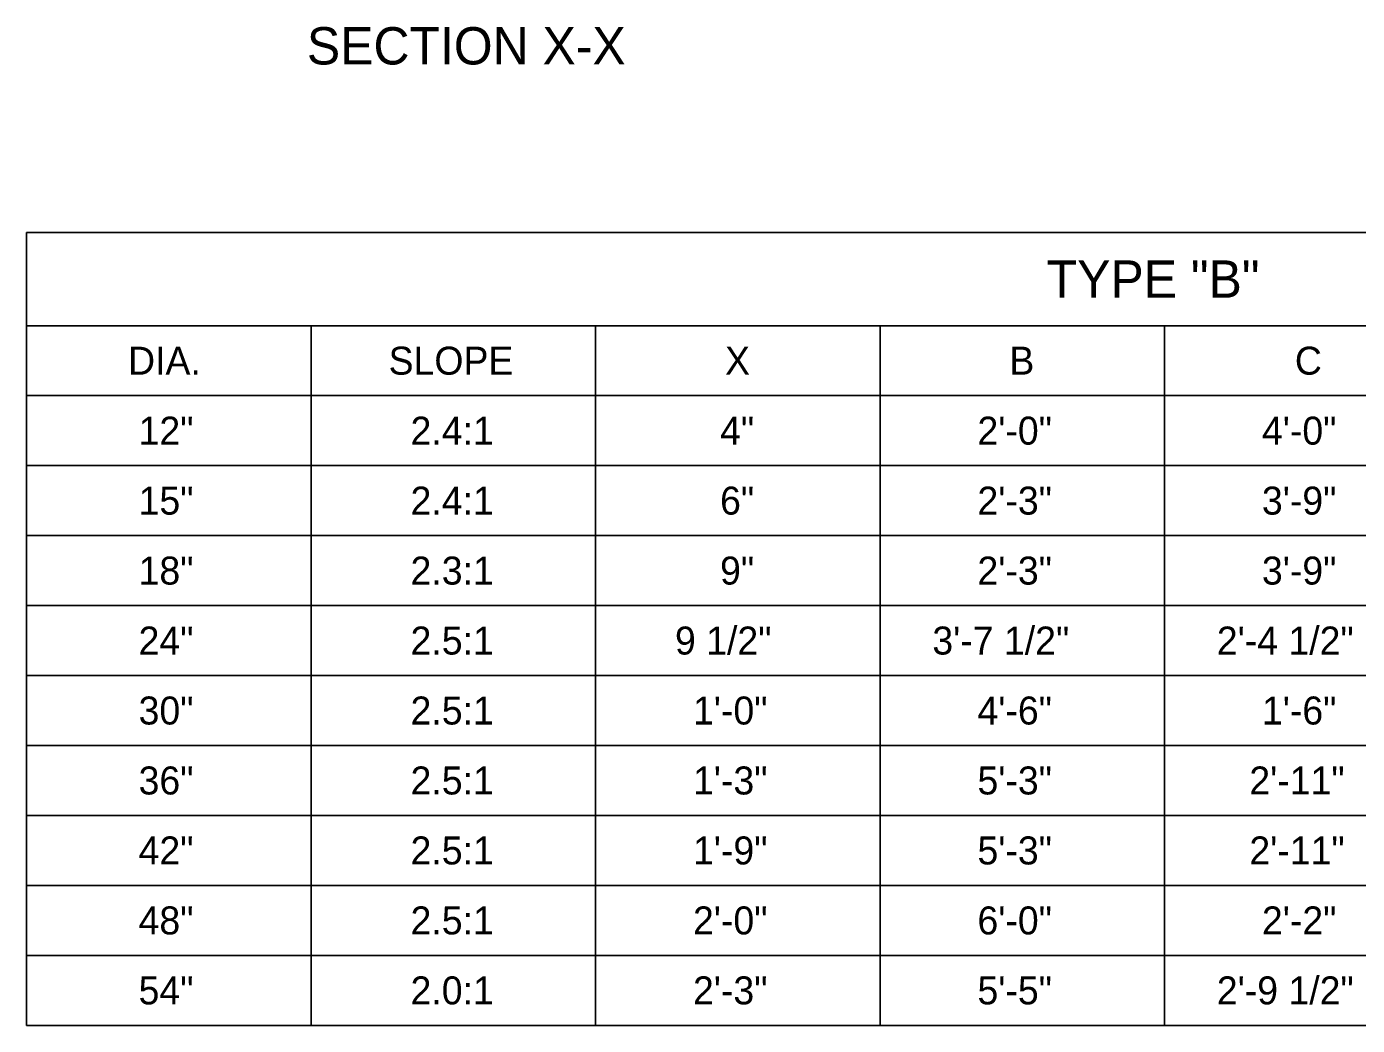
# Model space of a CAD drawing. Extents: x 49991.4 to 50021, y 49987.6 to 50011.4.
# Drawn here: x 50009.616 to 50012.469, y 49992.977 to 49995.118 of the extents above; entities that cross this region are included whole.
import ezdxf

# ---------------------------------------------------------------- set-up
doc = ezdxf.new("R2010")
doc.units = 0
doc.layers.add('Level 2', color=7, linetype='Continuous')

msp = doc.modelspace()

# ---------------------------------------------------------------- linework, layer by layer
at = {"layer": 'Level 2'}
for p, q in [((50009.6159, 49994.677), (50014.4959, 49994.677)), ((50009.6159, 49994.677), (50009.6159, 49992.977)), ((50009.6159, 49994.477), (50014.4959, 49994.477)), ((50010.2259, 49994.477), (50010.2259, 49992.977)), ((50010.8359, 49994.477), (50010.8359, 49992.977)), ((50011.4459, 49994.477), (50011.4459, 49992.977)), ((50012.0559, 49994.477), (50012.0559, 49992.977)), ((50009.6159, 49994.327), (50014.4959, 49994.327)), ((50009.6159, 49994.177), (50014.4959, 49994.177)), ((50009.6159, 49994.027), (50014.4959, 49994.027)), ((50009.6159, 49993.877), (50014.4959, 49993.877)), ((50009.6159, 49993.727), (50014.4959, 49993.727)), ((50009.6159, 49993.577), (50014.4959, 49993.577)), ((50009.6159, 49993.427), (50014.4959, 49993.427)), ((50009.6159, 49993.277), (50014.4959, 49993.277)), ((50009.6159, 49993.127), (50014.4959, 49993.127)), ((50009.6159, 49992.977), (50014.4959, 49992.977))]:
    msp.add_line(p, q, dxfattribs=at)

# ---------------------------------------------------------------- texts
for s, height, p in [('SECTION X-X', 0.08, (50010.2169, 49995.037)), ('TYPE "B"', 0.08, (50011.8033, 49994.537)), ('DIA.', 0.06, (50009.8334, 49994.372)), ('SLOPE', 0.06, (50010.3921, 49994.372)), ('X', 0.06, (50011.1135, 49994.372)), ('B', 0.06, (50011.7232, 49994.372)), ('C', 0.06, (50012.3354, 49994.372)), ('12"', 0.06, (50009.856, 49994.222)), ('2.4:1', 0.06, (50010.4392, 49994.222)), ('4"', 0.06, (50011.1029, 49994.222)), ('2\'-0"', 0.06, (50011.6548, 49994.222)), ('4\'-0"', 0.06, (50012.2648, 49994.222)), ('15"', 0.06, (50009.856, 49994.072)), ('2.4:1', 0.06, (50010.4392, 49994.072)), ('6"', 0.06, (50011.1029, 49994.072)), ('2\'-3"', 0.06, (50011.6548, 49994.072)), ('3\'-9"', 0.06, (50012.2648, 49994.072)), ('18"', 0.06, (50009.856, 49993.922)), ('2.3:1', 0.06, (50010.4392, 49993.922)), ('9"', 0.06, (50011.1029, 49993.922)), ('2\'-3"', 0.06, (50011.6548, 49993.922)), ('3\'-9"', 0.06, (50012.2648, 49993.922)), ('24"', 0.06, (50009.856, 49993.772)), ('2.5:1', 0.06, (50010.4392, 49993.772)), ('9 1/2"', 0.06, (50011.0062, 49993.772)), ('3\'-7 1/2"', 0.06, (50011.5581, 49993.772)), ('2\'-4 1/2"', 0.06, (50012.1681, 49993.772)), ('30"', 0.06, (50009.856, 49993.622)), ('2.5:1', 0.06, (50010.4392, 49993.622)), ('1\'-0"', 0.06, (50011.0448, 49993.622)), ('4\'-6"', 0.06, (50011.6548, 49993.622)), ('1\'-6"', 0.06, (50012.2648, 49993.622)), ('36"', 0.06, (50009.856, 49993.472)), ('2.5:1', 0.06, (50010.4392, 49993.472)), ('1\'-3"', 0.06, (50011.0448, 49993.472)), ('5\'-3"', 0.06, (50011.6548, 49993.472)), ('2\'-11"', 0.06, (50012.2378, 49993.472)), ('42"', 0.06, (50009.856, 49993.322)), ('2.5:1', 0.06, (50010.4392, 49993.322)), ('1\'-9"', 0.06, (50011.0448, 49993.322)), ('5\'-3"', 0.06, (50011.6548, 49993.322)), ('2\'-11"', 0.06, (50012.2379, 49993.322)), ('48"', 0.06, (50009.856, 49993.172)), ('2.5:1', 0.06, (50010.4392, 49993.172)), ('2\'-0"', 0.06, (50011.0448, 49993.172)), ('6\'-0"', 0.06, (50011.6548, 49993.172)), ('2\'-2"', 0.06, (50012.2648, 49993.172)), ('54"', 0.06, (50009.856, 49993.022)), ('2.0:1', 0.06, (50010.4392, 49993.022)), ('2\'-3"', 0.06, (50011.0448, 49993.022)), ('5\'-5"', 0.06, (50011.6548, 49993.022)), ('2\'-9 1/2"', 0.06, (50012.1681, 49993.022))]:
    msp.add_text(s, height=height, dxfattribs=at).set_placement(p)

doc.saveas('drawing.dxf')
